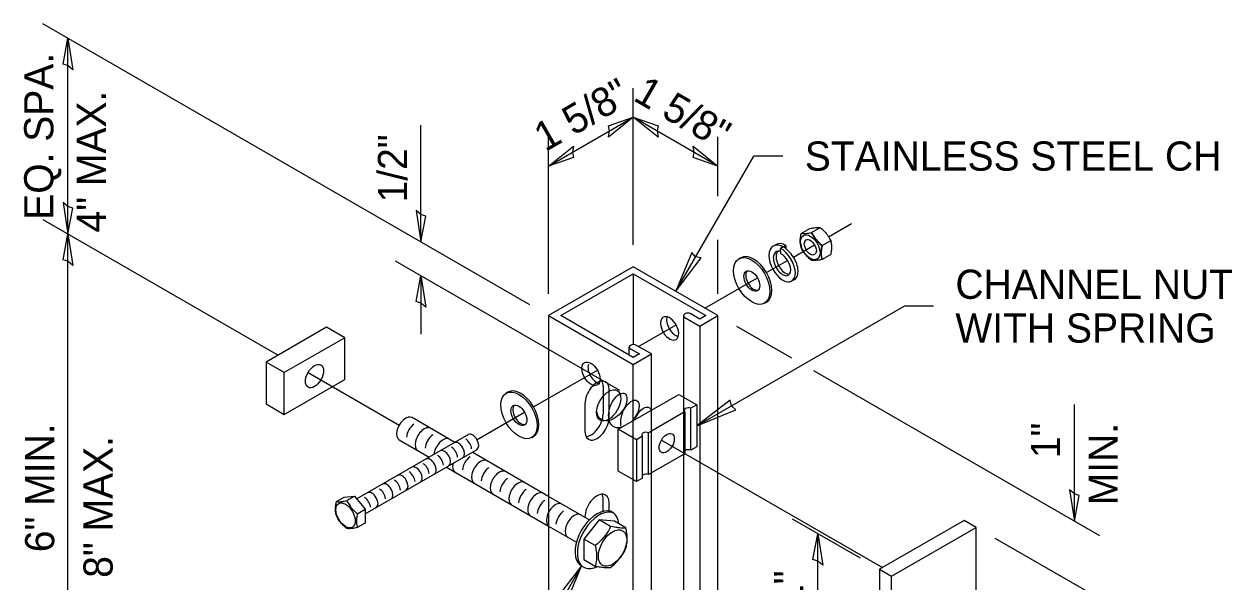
# Model space of a CAD drawing. Extents: x 99862 to 103151, y 100000 to 102076.
# Drawn here: x 101614 to 102264, y 100691 to 100996 of the extents above; entities that cross this region are included whole.
import ezdxf

# ---------------------------------------------------------------- set-up
doc = ezdxf.new("R2010")
doc.units = 0
for name, color, linetype in [('Level 1', 7, 'Continuous'), ('Level 12', 7, 'Continuous'), ('Level 15', 7, 'Continuous'), ('Level 16', 7, 'Continuous'), ('Level 2', 7, 'Continuous'), ('Level 20', 7, 'Continuous'), ('Level 3', 7, 'Continuous'), ('Level 4', 7, 'Continuous'), ('Level 5', 7, 'Continuous'), ('Level 6', 7, 'Continuous'), ('Level 7', 7, 'Continuous'), ('Level 8', 7, 'Continuous')]:
    doc.layers.add(name, color=color, linetype=linetype)

msp = doc.modelspace()

# ---------------------------------------------------------------- linework, layer by layer
at = {"layer": 'Level 1'}
for p, q in [((101948.05, 100863.1), (101901.65, 100836.31)), ((101994.46, 100836.31), (101948.05, 100863.1)), ((101908.28, 100836.31), (101948.05, 100859.27)), ((101948.05, 100859.27), (101987.83, 100836.31)), ((101948.05, 100859.27), (101948.05, 100820.39)), ((101901.65, 100836.31), (101901.65, 100346.41)), ((101901.65, 100836.31), (101948.05, 100809.52)), ((101948.05, 100813.34), (101908.28, 100836.31)), ((101975.53, 100836.31), (101975.53, 100342.05)), ((101976.21, 100835.36), (101984.51, 100830.57)), ((101984.51, 100834.39), (101979.53, 100837.27)), ((101987.83, 100836.31), (101984.51, 100834.39)), ((101984.51, 100830.57), (101994.46, 100836.31)), ((101994.46, 100342.6), (101994.46, 100836.31)), ((101984.51, 100830.57), (101984.51, 100336.86)), ((101945.8, 100814.64), (101945.8, 100819.04)), ((101946.49, 100818.09), (101951.38, 100815.26)), ((101951.38, 100815.26), (101948.05, 100813.34)), ((101948.05, 100809.52), (101958, 100815.26)), ((101958, 100815.26), (101949.8, 100820)), ((101958, 100325.36), (101958, 100815.26)), ((101948.05, 100319.62), (101948.05, 100809.52)), ((101931.48, 100797.63), (101931.48, 100782.32)), ((101934.8, 100780.41), (101934.8, 100795.72)), ((101921.54, 100788.06), (101921.54, 100772.75)), ((101931.48, 100728.99), (101931.48, 100735.55)), ((101934.8, 100729.14), (101934.8, 100733.63))]:
    msp.add_line(p, q, dxfattribs=at)
for centre, major_axis, start_param, end_param in [((101967.94, 100829.28), (3.52, -6.09), 0.252252, 6.533776), ((101971.26, 100831.2), (-3.52, 6.09), 0.490883, 2.65071), ((101977.86, 100836.31), (2.33, 0), 2.356194, 3.926991), ((101977.88, 100836.32), (2.33, 0), 0.785398, 2.356194), ((101948.13, 100819.04), (2.33, 0), 2.356194, 3.926991), ((101948.16, 100819.05), (2.33, 0), 0.785398, 2.356194), ((101928.17, 100805.15), (3.52, -6.09), 3.632475, 5.792303), ((101928.17, 100791.89), (4.69, 8.12), 5.497787, 8.63938), ((101924.85, 100793.8), (-4.69, -8.12), 2.356194, 2.780226), ((101928.17, 100776.58), (4.69, 8.12), 2.356194, 5.497787), ((101924.85, 100778.49), (-4.69, -8.12), 0.361367, 2.356194), ((101928.17, 100729.8), (4.69, 8.12), 5.497787, 8.63938), ((101924.85, 100731.72), (-4.69, -8.12), 2.356194, 2.780226)]:
    msp.add_ellipse(centre, major_axis=major_axis, ratio=0.57735, start_param=start_param, end_param=end_param, dxfattribs=at)
msp.add_ellipse((101924.85, 100804.41), major_axis=(3.52, -6.09), ratio=0.57735, dxfattribs=at)
at = {"layer": 'Level 12'}
msp.add_line((101932.85, 100737.92), (101932.85, 100737.92), dxfattribs=at)
at = {"layer": 'Level 15'}
for p, q in [((101891.26, 100842.31), (101624.34, 100996.41)), ((101638.2, 100881.11), (101638.2, 100988.41)), ((101948.05, 100875.1), (101948.05, 100961.1)), ((101901.65, 100918.31), (101948.05, 100945.1)), ((101994.46, 100918.31), (101948.05, 100945.1)), ((101831.65, 100876.72), (101831.65, 100940.72)), ((101901.65, 100848.31), (101901.65, 100934.31)), ((101994.46, 100901.89), (101994.46, 100934.31)), ((101971.26, 100849.7), (102014.05, 100923.82)), ((102030.05, 100923.82), (102014.05, 100923.82)), ((101638.2, 100605.8), (101638.2, 100881.11)), ((101994.46, 100848.31), (101994.46, 100877.89)), ((101940.75, 100795.23), (101817.79, 100866.22)), ((101831.65, 100858.22), (101831.65, 100826.22)), ((101982.92, 100775.89), (102096.57, 100841.51)), ((102112.57, 100841.51), (102096.57, 100841.51)), ((102035.01, 100812.9), (102004.85, 100830.31)), ((102203.66, 100715.52), (102047.01, 100805.97)), ((102189.8, 100723.55), (102189.8, 100787.55)), ((102072.54, 100703.18), (102035.3, 100724.68)), ((102049.16, 100656.1), (102049.16, 100716.68)), ((102202.6, 100681.68), (102146.36, 100714.14)), ((101919.66, 100698.98), (101879.16, 100628.84))]:
    msp.add_line(p, q, dxfattribs=at)
for points in [[(101638.2, 100988.41), (101640.87, 100971.14), (101638.2, 100973.41), (101635.53, 100974.22)], [(101948.05, 100945.1), (101934.43, 100934.15), (101935.06, 100937.6), (101934.43, 100940.32)], [(101948.05, 100945.1), (101961.68, 100940.32), (101961.04, 100937.6), (101961.68, 100934.15)], [(101901.65, 100918.31), (101915.27, 100929.26), (101914.64, 100925.81), (101915.27, 100923.09)], [(101994.46, 100918.31), (101980.84, 100923.09), (101981.47, 100925.81), (101980.84, 100929.26)], [(101638.2, 100881.11), (101640.87, 100895.3), (101638.2, 100896.11), (101635.53, 100898.38)], [(101831.65, 100876.72), (101834.32, 100890.91), (101831.65, 100891.72), (101828.98, 100894)], [(101638.2, 100881.11), (101640.87, 100863.84), (101638.2, 100866.11), (101635.53, 100866.92)], [(101971.26, 100849.7), (101985.25, 100867.98), (101982.14, 100868.56), (101980.09, 100870.97)], [(101831.65, 100858.22), (101834.32, 100840.94), (101831.65, 100843.22), (101828.98, 100844.03)], [(101982.92, 100775.89), (102004.19, 100784.72), (102001.78, 100786.78), (102001.2, 100789.89)], [(102189.81, 100723.52), (102192.48, 100737.71), (102189.81, 100738.52), (102187.14, 100740.8)], [(102049.16, 100716.68), (102051.83, 100699.41), (102049.16, 100701.68), (102046.49, 100702.49)], [(101919.66, 100698.98), (101905.66, 100680.71), (101908.77, 100680.13), (101910.83, 100677.72)]]:
    msp.add_lwpolyline(points, close=True, dxfattribs=at)
at = {"layer": 'Level 16'}
for p, q in [((101624.34, 100889.1), (101753.39, 100814.62)), ((102055.04, 100879.57), (102067.65, 100886.85)), ((102035.76, 100868.44), (102047.41, 100875.16)), ((102021.01, 100859.92), (102032.6, 100866.61)), ((101987.28, 100840.45), (102016.07, 100857.07)), ((101950.83, 100819.4), (101971.46, 100831.31)), ((101769.77, 100805.16), (101819.79, 100776.29)), ((101893.36, 100786.23), (101928.37, 100806.43)), ((101862.38, 100768.34), (101888.42, 100783.37)), ((101963.42, 100768.02), (102084.58, 100698.13))]:
    msp.add_line(p, q, dxfattribs=at)
at = {"layer": 'Level 2'}
for p, q in [((102129.34, 100723.97), (102082.93, 100697.18)), ((102135.97, 100720.14), (102129.34, 100723.97)), ((102089.56, 100693.35), (102135.97, 100720.14)), ((102135.97, 100675.47), (102135.97, 100720.14)), ((102082.93, 100697.18), (102089.56, 100693.35)), ((102082.93, 100697.18), (102082.93, 100647.43)), ((102089.56, 100643.6), (102089.56, 100693.35))]:
    msp.add_line(p, q, dxfattribs=at)
at = {"layer": 'Level 3'}
for p, q in [((101958, 100784.47), (101972.98, 100793.12)), ((101972.98, 100793.12), (101975.53, 100791.64)), ((101975.53, 100791.64), (101982.92, 100787.38)), ((101939.83, 100773.98), (101958, 100784.47)), ((101975.53, 100783.11), (101958, 100772.99)), ((101975.53, 100783.11), (101976.29, 100783.55)), ((101976.29, 100783.55), (101976.29, 100760.59)), ((101982.92, 100787.38), (101979.61, 100785.46)), ((101979.61, 100762.5), (101979.61, 100785.46)), ((101982.92, 100787.38), (101982.92, 100764.41)), ((101949.78, 100768.24), (101939.83, 100773.98)), ((101939.83, 100751.02), (101939.83, 100773.98)), ((101953.09, 100770.15), (101949.78, 100768.24)), ((101953.09, 100747.19), (101953.09, 100770.15)), ((101953.39, 100771.93), (101953.33, 100771.89)), ((101953.39, 100771.93), (101953.33, 100771.89)), ((101958, 100772.99), (101956.41, 100772.07)), ((101956.41, 100749.1), (101956.41, 100772.07)), ((101949.78, 100768.24), (101949.78, 100745.28)), ((101982.92, 100764.41), (101979.61, 100762.5)), ((101975.53, 100760.15), (101958, 100750.03)), ((101975.53, 100760.15), (101976.29, 100760.59)), ((101976.59, 100762.36), (101976.53, 100762.33)), ((101949.78, 100745.28), (101939.83, 100751.02)), ((101958, 100750.03), (101956.41, 100749.1)), ((101953.09, 100747.19), (101949.78, 100745.28)), ((101953.39, 100748.97), (101953.33, 100748.93))]:
    msp.add_line(p, q, dxfattribs=at)
for centre, start_param, end_param in [((101978.17, 100784.34), 5.497787, 6.912154), ((101978.24, 100784.38), 4.082321, 5.497787), ((101954.97, 100770.94), 5.497787, 6.913253), ((101955.04, 100770.98), 4.082321, 5.497787), ((101978.24, 100761.41), 4.082321, 5.497787), ((101978.17, 100761.38), 5.497787, 5.653117), ((101978.17, 100761.38), 0.630068, 0.630068), ((101954.97, 100747.98), 5.497787, 5.653117), ((101954.97, 100747.98), 0.630068, 0.630068), ((101955.04, 100748.02), 4.082321, 5.497787)]:
    msp.add_ellipse(centre, major_axis=(-2.33, 0), ratio=0.57735, start_param=start_param, end_param=end_param, dxfattribs=at)
msp.add_ellipse((101966.35, 100766.33), major_axis=(2.93, 5.07), ratio=0.57735, dxfattribs=at)
at = {"layer": 'Level 4'}
for p, q in [((101857.69, 100771.04), (101796.54, 100735.74)), ((101801.05, 100727.51), (101862.38, 100762.92)), ((101789.57, 100736.75), (101795.31, 100737.27)), ((101791.05, 100734.81), (101795.31, 100737.27)), ((101795.31, 100737.27), (101801.05, 100730.13)), ((101785.3, 100734.29), (101789.57, 100736.75)), ((101796.79, 100727.67), (101801.05, 100730.13)), ((101801.05, 100730.13), (101801.05, 100722.47)), ((101801.05, 100722.47), (101796.79, 100720.01))]:
    msp.add_line(p, q, dxfattribs=at)
for centre, start_param, end_param in [((101860.03, 100766.98), 3.141593, 6.283185), ((101848.42, 100760.28), 4.01075, 5.483611), ((101852.27, 100762.5), 3.141593, 6.283185), ((101856.15, 100764.74), 4.01075, 5.483611), ((101836.75, 100753.54), 3.141593, 6.283185), ((101840.68, 100755.81), 4.01075, 5.483611), ((101844.52, 100758.02), 3.141593, 6.283185), ((101825.12, 100746.83), 4.01075, 5.483611), ((101829, 100749.06), 3.141593, 6.283185), ((101832.88, 100751.3), 4.01075, 5.483611), ((101813.01, 100739.83), 3.141593, 6.283185), ((101817.15, 100742.22), 4.01075, 5.483611), ((101821.29, 100744.62), 3.141593, 6.283185), ((101804.82, 100735.1), 3.141593, 6.283185), ((101808.91, 100737.47), 4.011039, 5.48392), ((101800.73, 100732.74), 4.011039, 5.48392)]:
    msp.add_ellipse(centre, major_axis=(-2.34, 4.06), ratio=0.57735, start_param=start_param, end_param=end_param, dxfattribs=at)
msp.add_ellipse((101790.34, 100726.74), major_axis=(3.75, -6.5), ratio=0.57735, dxfattribs=at)
for points in [[(101785.3, 100726.64), (101785.16, 100727.18), (101785.04, 100727.73), (101784.87, 100728.91), (101784.83, 100729.54), (101784.83, 100730.84), (101784.87, 100731.5), (101785.04, 100732.88), (101785.16, 100733.58), (101785.3, 100734.29)], [(101785.3, 100734.29), (101785.95, 100734.21), (101786.73, 100734.19), (101788.68, 100734.36), (101789.81, 100734.56), (101791.05, 100734.81)], [(101791.05, 100734.81), (101791.7, 100733.47), (101792.47, 100732.17), (101794.42, 100729.74), (101795.56, 100728.67), (101796.79, 100727.67)], [(101791.05, 100719.5), (101789.81, 100720.5), (101788.67, 100721.59), (101786.72, 100724.01), (101785.95, 100725.3), (101785.3, 100726.64)], [(101796.79, 100727.67), (101796.64, 100726.96), (101796.52, 100726.25), (101796.36, 100724.87), (101796.31, 100724.21), (101796.31, 100722.91), (101796.36, 100722.29), (101796.52, 100721.11), (101796.64, 100720.55), (101796.79, 100720.01)], [(101796.79, 100720.01), (101795.55, 100719.76), (101794.41, 100719.57), (101792.46, 100719.39), (101791.69, 100719.41), (101791.05, 100719.5)]]:
    msp.add_open_spline(points, degree=3, dxfattribs=at)
at = {"layer": 'Level 5'}
for p, q in [((102006.95, 100868.04), (102005.96, 100867.47)), ((102020.02, 100843.11), (102021.01, 100843.69)), ((101879.3, 100794.34), (101878.31, 100793.77)), ((101892.37, 100769.41), (101893.36, 100769.99))]:
    msp.add_line(p, q, dxfattribs=at)
for centre, major_axis in [((102012.99, 100855.29), (-7.03, 12.18)), ((102012.99, 100855.29), (-3.08, 5.33)), ((101885.34, 100781.59), (-7.03, 12.18)), ((101885.34, 100781.59), (-3.08, 5.33))]:
    msp.add_ellipse(centre, major_axis=major_axis, ratio=0.57735, dxfattribs=at)
for centre, major_axis, start_param, end_param in [((102013.98, 100855.86), (-7.03, 12.18), 3.141593, 6.28318), ((102013.98, 100855.86), (-3.08, 5.33), 0.162038, 2.979555), ((101886.33, 100782.17), (-7.03, 12.18), 3.141593, 6.28318), ((101886.33, 100782.17), (-3.08, 5.33), 0.162038, 2.979555), ((101928.17, 100713.72), (8.51, 14.74), 5.605746, 9.495492), ((101929.37, 100713.03), (8.51, 14.74), 0.060106, 3.860312)]:
    msp.add_ellipse(centre, major_axis=major_axis, ratio=0.57735, start_param=start_param, end_param=end_param, dxfattribs=at)
at = {"layer": 'Level 6'}
for p, q in [((102040.03, 100881.36), (102044.73, 100884.07)), ((102045.77, 100881.87), (102050.47, 100884.58)), ((102024.89, 100874.56), (102026.32, 100875.32)), ((102030.15, 100874.09), (102028.74, 100873.18)), ((102030.18, 100874.08), (102031.6, 100874.84)), ((102031.6, 100874.84), (102031.55, 100873.19)), ((102051.51, 100874.73), (102056.21, 100877.44)), ((102028.89, 100870.25), (102028.74, 100873.18)), ((102056.21, 100869.79), (102051.51, 100867.08)), ((102034.61, 100855.19), (102036.11, 100855.97))]:
    msp.add_line(p, q, dxfattribs=at)
for major_axis in [(3.75, -6.5), (-2.34, 4.06)]:
    msp.add_ellipse((102045.06, 100873.81), major_axis=major_axis, ratio=0.57735, dxfattribs=at)
for centre, major_axis, ratio, start_param, end_param in [((102030.03, 100864.94), (-5.14, 9.62), 0.597856, 5.534976, 7.084707), ((102031.46, 100865.7), (-5.14, 9.62), 0.597856, 5.534976, 6.283185), ((102030.66, 100865.4), (-5.9, 9.18), 0.544801, 3.902515, 5.480817), ((102029.6, 100864.88), (5.01, -9.69), 0.544029, 3.970034, 7.094516), ((102029.6, 100864.88), (-3.32, 6.42), 0.544029, 0.780925, 3.925736), ((102029.87, 100865.04), (-3.41, 6.37), 0.597856, 5.759529, 7.052859), ((102031.1, 100865.66), (-3.32, 6.42), 0.544029, 0.781112, 2.924647), ((102031.38, 100865.74), (-3.41, 6.37), 0.597856, 0.161668, 0.762283), ((102029.16, 100864.53), (-5.9, 9.18), 0.544801, 3.912787, 5.471187), ((102029.31, 100864.45), (-3.9, 6.08), 0.544801, 3.919127, 5.49806), ((102031.1, 100865.66), (5.01, -9.69), 0.544029, 0, 0.811331)]:
    msp.add_ellipse(centre, major_axis=major_axis, ratio=ratio, start_param=start_param, end_param=end_param, dxfattribs=at)
for points in [[(102040.03, 100873.71), (102039.89, 100874.24), (102039.77, 100874.8), (102039.6, 100875.98), (102039.56, 100876.61), (102039.56, 100877.9), (102039.6, 100878.57), (102039.77, 100879.94), (102039.89, 100880.65), (102040.03, 100881.36)], [(102040.03, 100881.36), (102040.68, 100881.28), (102041.46, 100881.26), (102043.41, 100881.43), (102044.54, 100881.62), (102045.77, 100881.87)], [(102044.73, 100884.07), (102045.96, 100884.32), (102047.1, 100884.52), (102049.05, 100884.69), (102049.82, 100884.67), (102050.47, 100884.58)], [(102045.77, 100881.87), (102046.42, 100880.54), (102047.2, 100879.24), (102049.15, 100876.81), (102050.28, 100875.73), (102051.51, 100874.73)], [(102051.51, 100874.73), (102050.28, 100875.73), (102049.15, 100876.81), (102047.2, 100879.24), (102046.42, 100880.54), (102045.77, 100881.87)], [(102050.47, 100884.58), (102051.7, 100883.58), (102052.84, 100882.5), (102054.79, 100880.07), (102055.56, 100878.78), (102056.21, 100877.44)], [(102045.77, 100866.56), (102044.54, 100867.57), (102043.4, 100868.65), (102041.45, 100871.08), (102040.68, 100872.37), (102040.03, 100873.71)], [(102051.51, 100874.73), (102051.37, 100874.02), (102051.25, 100873.32), (102051.08, 100871.94), (102051.04, 100871.27), (102051.04, 100869.98), (102051.08, 100869.35), (102051.25, 100868.17), (102051.37, 100867.61), (102051.51, 100867.08)], [(102051.51, 100867.08), (102051.37, 100867.61), (102051.25, 100868.17), (102051.08, 100869.35), (102051.04, 100869.98), (102051.04, 100871.27), (102051.08, 100871.94), (102051.25, 100873.32), (102051.37, 100874.02), (102051.51, 100874.73)], [(102056.21, 100877.44), (102056.35, 100876.9), (102056.47, 100876.33), (102056.64, 100875.15), (102056.68, 100874.53), (102056.68, 100873.24), (102056.64, 100872.56), (102056.47, 100871.19), (102056.35, 100870.49), (102056.21, 100869.79)], [(102051.51, 100867.08), (102050.28, 100866.83), (102049.14, 100866.63), (102047.19, 100866.46), (102046.42, 100866.48), (102045.77, 100866.56)]]:
    msp.add_open_spline(points, degree=3, dxfattribs=at)
at = {"layer": 'Level 7'}
msp.add_ellipse((101934.56, 100787.1), major_axis=(4.69, 8.12), ratio=0.57735, dxfattribs=at)
for points in [[(101941.41, 100774.88), (101941.2, 100774.84), (101940.08, 100774.63), (101937.72, 100774.81), (101935.14, 100776.99), (101934.16, 100781.43), (101935.19, 100786.65), (101937.78, 100791.21), (101940.98, 100793.85), (101943.68, 100793.91), (101944.78, 100791.73), (101944.36, 100787.88), (101942.17, 100783.73), (101938.36, 100780.09), (101934, 100778.01), (101929.6, 100779.1), (101928.16, 100782.26), (101927.95, 100783.96)], [(101941.35, 100775.48), (101941.27, 100775.84), (101941.05, 100777.21), (101941.22, 100780.95), (101943.35, 100786.07), (101946.85, 100789.62), (101949.77, 100790.31), (101951.43, 100788.41), (101951.15, 100784.57), (101949.46, 100781.21), (101948.16, 100779.54), (101947.92, 100779.25)], [(101949.16, 100779.97), (101949.61, 100780.96), (101951.28, 100783.84), (101954.55, 100786.46), (101956.79, 100786.06), (101957.41, 100785.11), (101957.54, 100784.81)]]:
    msp.add_open_spline(points, degree=3, dxfattribs=at)
at = {"layer": 'Level 8'}
for p, q in [((101779.92, 100829.93), (101746.77, 100810.79)), ((101789.86, 100824.19), (101779.92, 100829.93)), ((101789.86, 100824.19), (101756.71, 100805.05)), ((101789.86, 100801.23), (101789.86, 100824.19)), ((101756.71, 100805.05), (101746.77, 100810.79)), ((101746.77, 100810.79), (101746.77, 100787.83)), ((101756.71, 100782.09), (101756.71, 100805.05)), ((101756.71, 100782.09), (101789.86, 100801.23)), ((101746.77, 100787.83), (101756.71, 100782.09)), ((101850.32, 100766.79), (101826.82, 100780.35)), ((101819.79, 100768.17), (101836.25, 100758.67)), ((101901.65, 100737.15), (101859.69, 100761.37)), ((101845.63, 100753.25), (101901.65, 100720.91)), ((101923.93, 100724.28), (101901.65, 100737.15)), ((101929.37, 100724.23), (101920.96, 100713.78)), ((101935.61, 100720.63), (101929.37, 100724.23)), ((101937.77, 100723.48), (101929.37, 100724.23)), ((101901.65, 100720.91), (101916.9, 100712.1)), ((101944.01, 100719.88), (101937.77, 100723.48)), ((101927.2, 100710.17), (101920.96, 100713.78)), ((101920.96, 100713.78), (101920.96, 100702.57)), ((101920.96, 100702.57), (101927.2, 100698.97))]:
    msp.add_line(p, q, dxfattribs=at)
for centre, major_axis in [((101773.29, 100803.14), (-3.52, -6.09)), ((101936.65, 100708.82), (5.49, 9.51))]:
    msp.add_ellipse(centre, major_axis=major_axis, ratio=0.57735, dxfattribs=at)
for centre, major_axis, start_param, end_param in [((101823.3, 100774.26), (-3.52, -6.09), 3.141593, 6.283191), ((101828.59, 100771.59), (3.55, 6.07), 0.942075, 2.218001), ((101833.43, 100768.42), (3.55, 6.07), 0, 3.141593), ((101838.83, 100765.61), (3.55, 6.07), 0.942075, 2.218001), ((101843.76, 100762.45), (3.55, 6.07), 0, 2.265792), ((101859.29, 100753.66), (3.55, 6.07), 0.942075, 2.218001), ((101864.32, 100750.58), (3.55, 6.07), 0, 3.141593), ((101854.03, 100756.52), (3.55, 6.07), 2.082557, 3.141593), ((101869.53, 100747.68), (3.55, 6.07), 0.942075, 2.218001), ((101874.58, 100744.66), (3.55, 6.07), 0, 3.141593), ((101879.76, 100741.7), (3.55, 6.07), 0.942075, 2.218001), ((101884.88, 100738.71), (3.55, 6.07), 0, 3.141593), ((101889.99, 100735.72), (3.55, 6.07), 0.942075, 2.218001), ((101895.14, 100732.79), (3.55, 6.07), 0, 3.133845), ((101900.23, 100729.75), (3.55, 6.07), 0.942075, 2.218001), ((101905.39, 100726.87), (3.54, 6.08), 0, 3.141593), ((101910.55, 100723.92), (3.54, 6.08), 0.942075, 2.218001), ((101915.67, 100720.94), (3.54, 6.08), 0, 3.141593)]:
    msp.add_ellipse(centre, major_axis=major_axis, ratio=0.57735, start_param=start_param, end_param=end_param, dxfattribs=at)
for points in [[(101935.61, 100720.63), (101934.66, 100718.67), (101933.53, 100716.78), (101930.68, 100713.23), (101929.01, 100711.64), (101927.2, 100710.17)], [(101944.01, 100719.88), (101943.06, 100719.76), (101941.94, 100719.73), (101939.09, 100719.98), (101937.41, 100720.26), (101935.61, 100720.63)], [(101944.01, 100708.67), (101944.23, 100709.47), (101944.4, 100710.3), (101944.64, 100712.03), (101944.71, 100712.93), (101944.71, 100714.83), (101944.64, 100715.82), (101944.4, 100717.83), (101944.22, 100718.85), (101944.01, 100719.88)], [(101927.2, 100710.17), (101927.41, 100709.14), (101927.59, 100708.12), (101927.83, 100706.12), (101927.9, 100705.12), (101927.9, 100703.23), (101927.83, 100702.32), (101927.59, 100700.59), (101927.41, 100699.76), (101927.2, 100698.97)], [(101935.61, 100698.22), (101937.41, 100699.68), (101939.07, 100701.26), (101941.93, 100704.81), (101943.06, 100706.71), (101944.01, 100708.67)], [(101927.2, 100698.97), (101929, 100698.6), (101930.67, 100698.32), (101933.52, 100698.06), (101934.66, 100698.09), (101935.61, 100698.22)]]:
    msp.add_open_spline(points, degree=3, dxfattribs=at)

# ---------------------------------------------------------------- texts
at = {"layer": 'Level 20'}
for s, rotation, p in [('EQ. SPA.', 90.00011, (101630.2, 100888.87)), ('1 5/8"', 30, (101899.77, 100925.86)), ('1 5/8"', 330.0064, (101947.34, 100954.71)), ('4" MAX.', 90.00011, (101658.99, 100881.92)), ('1/2"', 90.00011, (101824.08, 100898.38)), ('STAINLESS STEEL CHANNEL', 360, (102042.04, 100915.82)), ('CHANNEL NUT', 360, (102124.57, 100845.51)), ('WITH SPRING (TYP.)', 360, (102124.57, 100821.51)), ('1"', 90.00011, (102181.92, 100758.1)), ('6" MIN.', 90.00011, (101630.69, 100706.55)), ('MIN.', 90.00011, (102213.56, 100732.29)), ('8" MAX.', 90.00011, (101662.69, 100692.5)), ('1"', 90.00011, (102041.16, 100677.03))]:
    msp.add_text(s, height=16, rotation=rotation, dxfattribs=at).set_placement(p)

doc.saveas('drawing.dxf')
